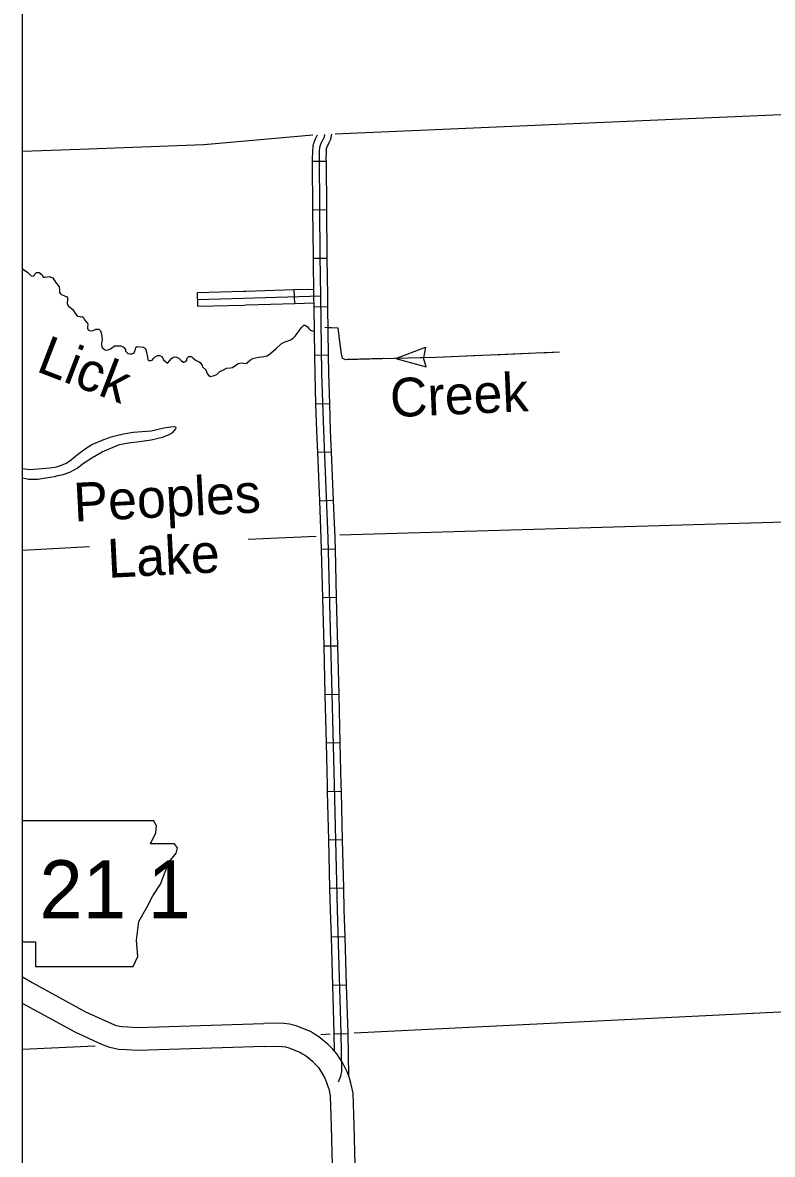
# Model space of a CAD drawing. Extents: x 1164457 to 1439835, y 1590918 to 1773502.
# Drawn here: x 1246398 to 1254561, y 1653578 to 1665903 of the extents above; entities that cross this region are included whole.
import ezdxf

# ---------------------------------------------------------------- set-up
doc = ezdxf.new("R2010")
doc.units = 0
for name, color, linetype in [('Level 1', 7, 'Continuous'), ('Level 10', 7, 'Continuous'), ('Level 21', 7, 'Continuous'), ('Level 32', 7, 'Continuous'), ('Level 35', 7, 'Continuous'), ('Level 43', 7, 'Continuous'), ('Level 45', 7, 'Continuous'), ('Level 5', 7, 'Continuous'), ('R_Draft', 7, 'Continuous')]:
    doc.layers.add(name, color=color, linetype=linetype)

msp = doc.modelspace()

# ---------------------------------------------------------------- linework, layer by layer
at = {"layer": 'Level 1'}
for points in [[(1260189, 1665083), (1255108, 1664914), (1254987, 1664912), (1249802, 1664688)], [(1249558, 1664676), (1248370, 1664574), (1247021, 1664523), (1246398, 1664499)]]:
    msp.add_lwpolyline(points, dxfattribs=at)
at = {"layer": 'Level 10'}
for points in [[(1246398, 1655512), (1246503, 1655450), (1247083, 1655130), (1247364, 1655002), (1247418, 1654982), (1247478, 1654969), (1247543, 1654965), (1247649, 1654960), (1249023, 1655002)], [(1249031, 1654753), (1247648, 1654710), (1247530, 1654715), (1247442, 1654720), (1247347, 1654742), (1247269, 1654770), (1246971, 1654907), (1246398, 1655222)], [(1250061, 1651737), (1250008, 1653894), (1249995, 1654244), (1249973, 1654353), (1249956, 1654409), (1249934, 1654468), (1249911, 1654519), (1249880, 1654577), (1249852, 1654621), (1249818, 1654672), (1249772, 1654726), (1249721, 1654778), (1249665, 1654823), (1249622, 1654858), (1249577, 1654885), (1249531, 1654914), (1249375, 1654978), (1249304, 1654994), (1249243, 1655002), (1249157, 1655006), (1249024, 1655002)], [(1249030, 1654753), (1249155, 1654756), (1249222, 1654753), (1249259, 1654748), (1249298, 1654739), (1249417, 1654690), (1249446, 1654672), (1249478, 1654653), (1249509, 1654628), (1249553, 1654593), (1249587, 1654557), (1249618, 1654522), (1249641, 1654486), (1249664, 1654451), (1249687, 1654408), (1249703, 1654373), (1249719, 1654329), (1249730, 1654291), (1249746, 1654214), (1249758, 1653886), (1249811, 1651731)]]:
    msp.add_lwpolyline(points, dxfattribs=at)
at = {"layer": 'Level 21'}
for p, q in [((1247857, 1657154), (1247822, 1657213)), ((1247848, 1657078), (1247857, 1657154)), ((1247789, 1656960), (1247848, 1657078)), ((1248051, 1656960), (1247789, 1656960)), ((1248085, 1656917), (1248051, 1656960)), ((1248068, 1656858), (1248085, 1656917)), ((1247992, 1656765), (1248068, 1656858)), ((1247950, 1656655), (1247992, 1656765)), ((1247899, 1656520), (1247950, 1656655)), ((1247815, 1656393), (1247899, 1656520)), ((1247755, 1656274), (1247815, 1656393)), ((1247662, 1656114), (1247755, 1656274)), ((1247637, 1655911), (1247662, 1656114)), ((1246398, 1655901), (1246410, 1655894)), ((1246410, 1655894), (1246537, 1655894)), ((1246537, 1655894), (1246537, 1655623)), ((1247654, 1655733), (1247637, 1655911)), ((1247603, 1655623), (1247654, 1655733)), ((1246537, 1655623), (1247603, 1655623))]:
    msp.add_line(p, q, dxfattribs=at)
msp.add_lwpolyline([(1246398, 1657213), (1247822, 1657213)], dxfattribs=at)
at = {"layer": 'Level 32'}
for p, q in [((1249705, 1664391), (1249555, 1664390)), ((1249709, 1663863), (1249559, 1663862)), ((1249714, 1663336), (1249564, 1663333)), ((1249722, 1662808), (1249572, 1662806)), ((1249729, 1662280), (1249579, 1662278)), ((1249742, 1661753), (1249592, 1661749)), ((1249761, 1661226), (1249611, 1661220)), ((1249783, 1660699), (1249633, 1660693)), ((1249803, 1660170), (1249653, 1660166)), ((1249816, 1659642), (1249666, 1659638)), ((1249830, 1659114), (1249680, 1659111)), ((1249843, 1658587), (1249693, 1658583)), ((1249856, 1658059), (1249706, 1658055)), ((1249869, 1657531), (1249719, 1657527)), ((1249882, 1657003), (1249732, 1656999)), ((1249894, 1656475), (1249744, 1656472)), ((1249909, 1655948), (1249759, 1655943)), ((1249925, 1655420), (1249775, 1655415)), ((1249941, 1654892), (1249791, 1654888))]:
    msp.add_line(p, q, dxfattribs=at)
for points in [[(1249555, 1664390), (1249554, 1664418), (1249556, 1664499), (1249560, 1664559), (1249569, 1664591), (1249580, 1664620), (1249588, 1664638), (1249610, 1664680)], [(1249837, 1654369), (1249864, 1654430), (1249875, 1654480), (1249866, 1654899), (1249825, 1656240), (1249792, 1657601), (1249725, 1660289), (1249676, 1661460), (1249657, 1662082), (1249645, 1662929), (1249638, 1663360), (1249629, 1664418), (1249631, 1664496), (1249634, 1664546), (1249640, 1664567), (1249649, 1664590), (1249656, 1664605), (1249669, 1664631), (1249684, 1664659), (1249689, 1664684)], [(1249705, 1664391), (1249704, 1664418), (1249706, 1664492), (1249708, 1664534), (1249711, 1664543), (1249718, 1664560), (1249724, 1664573), (1249735, 1664596), (1249755, 1664634), (1249766, 1664687)], [(1249559, 1663862), (1249555, 1664390)], [(1249709, 1663863), (1249705, 1664391)], [(1249564, 1663333), (1249563, 1663360), (1249559, 1663862)], [(1249714, 1663336), (1249713, 1663361), (1249709, 1663863)], [(1249572, 1662806), (1249570, 1662928), (1249564, 1663333)], [(1249722, 1662808), (1249720, 1662930), (1249714, 1663336)], [(1249579, 1662278), (1249572, 1662806)], [(1249729, 1662280), (1249722, 1662808)], [(1249592, 1661749), (1249582, 1662080), (1249579, 1662278)], [(1249742, 1661753), (1249732, 1662083), (1249729, 1662280)], [(1249611, 1661220), (1249601, 1661457), (1249592, 1661749)], [(1249761, 1661226), (1249751, 1661462), (1249742, 1661753)], [(1249633, 1660693), (1249611, 1661220)], [(1249783, 1660699), (1249761, 1661226)], [(1249653, 1660166), (1249650, 1660287), (1249633, 1660693)], [(1249803, 1660170), (1249800, 1660292), (1249783, 1660699)], [(1249666, 1659638), (1249653, 1660166)], [(1249816, 1659642), (1249803, 1660170)], [(1249680, 1659111), (1249666, 1659638)], [(1249830, 1659114), (1249816, 1659642)], [(1249693, 1658583), (1249680, 1659111)], [(1249843, 1658587), (1249830, 1659114)], [(1249706, 1658055), (1249693, 1658583)], [(1249856, 1658059), (1249843, 1658587)], [(1249719, 1657527), (1249717, 1657600), (1249706, 1658055)], [(1249869, 1657531), (1249867, 1657603), (1249856, 1658059)], [(1249732, 1656999), (1249719, 1657527)], [(1249882, 1657003), (1249869, 1657531)], [(1249744, 1656472), (1249732, 1656999)], [(1249894, 1656475), (1249882, 1657003)], [(1249759, 1655943), (1249750, 1656238), (1249744, 1656472)], [(1249909, 1655948), (1249900, 1656242), (1249894, 1656475)], [(1249775, 1655415), (1249759, 1655943)], [(1249925, 1655420), (1249909, 1655948)], [(1249791, 1654888), (1249791, 1654897), (1249775, 1655415)], [(1249941, 1654892), (1249941, 1654901), (1249925, 1655420)], [(1249795, 1654709), (1249791, 1654888)], [(1249951, 1654432), (1249941, 1654892)]]:
    msp.add_lwpolyline(points, dxfattribs=at)
at = {"layer": 'Level 35'}
msp.add_line((1249158, 1662355), (1249211, 1662404), dxfattribs=at)
for points in [[(1246398, 1663220), (1246455, 1663183), (1246492, 1663147), (1246516, 1663141), (1246529, 1663154), (1246538, 1663173), (1246550, 1663181), (1246565, 1663183), (1246578, 1663181), (1246609, 1663156), (1246621, 1663131), (1246641, 1663131), (1246670, 1663135), (1246688, 1663137), (1246715, 1663126), (1246727, 1663122), (1246756, 1663078), (1246794, 1663024), (1246799, 1662991), (1246799, 1662964), (1246815, 1662945), (1246860, 1662925), (1246874, 1662922), (1246886, 1662905), (1246886, 1662878), (1246882, 1662859), (1246882, 1662841), (1246896, 1662814), (1246945, 1662780), (1246973, 1662733), (1246995, 1662706), (1247019, 1662701), (1247030, 1662699), (1247048, 1662704), (1247059, 1662692), (1247073, 1662665)], [(1247073, 1662665), (1247098, 1662639), (1247104, 1662632), (1247108, 1662608), (1247106, 1662593), (1247105, 1662576), (1247113, 1662558), (1247135, 1662546), (1247166, 1662549), (1247196, 1662564), (1247216, 1662564), (1247228, 1662564), (1247245, 1662548), (1247253, 1662526), (1247260, 1662487), (1247265, 1662450), (1247257, 1662414), (1247257, 1662392), (1247265, 1662365), (1247299, 1662335), (1247328, 1662340), (1247355, 1662352), (1247382, 1662374), (1247402, 1662382), (1247420, 1662382), (1247444, 1662382), (1247466, 1662382), (1247498, 1662367), (1247518, 1662345), (1247518, 1662326), (1247542, 1662299), (1247566, 1662296), (1247586, 1662296), (1247609, 1662304), (1247625, 1662336), (1247632, 1662366), (1247646, 1662377), (1247683, 1662374), (1247714, 1662367), (1247734, 1662355), (1247748, 1662313), (1247758, 1662259), (1247760, 1662237), (1247770, 1662223), (1247792, 1662223), (1247807, 1662228), (1247822, 1662244), (1247841, 1662262), (1247868, 1662279), (1247893, 1662279), (1247917, 1662262), (1247933, 1662230), (1247974, 1662196), (1247999, 1662222), (1248020, 1662247), (1248036, 1662261), (1248055, 1662262), (1248074, 1662261), (1248097, 1662249), (1248124, 1662225), (1248144, 1662206), (1248158, 1662206), (1248177, 1662215), (1248187, 1662228), (1248187, 1662247), (1248195, 1662257), (1248209, 1662267), (1248220, 1662267), (1248236, 1662267), (1248254, 1662249), (1248286, 1662223), (1248313, 1662212), (1248330, 1662200), (1248351, 1662168), (1248358, 1662156), (1248392, 1662122), (1248407, 1662083), (1248417, 1662066), (1248439, 1662051), (1248473, 1662056), (1248513, 1662071), (1248545, 1662103), (1248586, 1662120), (1248618, 1662141), (1248659, 1662144), (1248684, 1662147), (1248709, 1662166), (1248750, 1662191), (1248778, 1662198), (1248804, 1662195), (1248822, 1662191), (1248843, 1662195), (1248854, 1662208), (1248880, 1662230), (1248905, 1662244), (1248934, 1662254), (1248966, 1662261), (1249024, 1662266), (1249060, 1662276), (1249099, 1662304), (1249158, 1662355)], [(1249211, 1662404), (1249245, 1662424), (1249278, 1662435), (1249315, 1662450), (1249343, 1662465), (1249366, 1662488), (1249408, 1662546), (1249430, 1662580), (1249459, 1662607), (1249474, 1662609), (1249490, 1662599), (1249498, 1662590), (1249513, 1662571), (1249532, 1662552), (1249576, 1662538)], [(1246786, 1660970), (1246841, 1660982), (1246913, 1661008), (1246990, 1661051), (1247061, 1661104), (1247152, 1661165), (1247263, 1661227), (1247451, 1661307), (1247549, 1661326), (1247669, 1661342), (1247799, 1661361), (1247921, 1661389), (1247987, 1661413), (1248034, 1661439), (1248067, 1661481), (1248071, 1661492), (1248065, 1661499), (1248037, 1661502), (1247934, 1661485), (1247798, 1661455), (1247601, 1661441), (1247498, 1661420), (1247360, 1661388), (1247277, 1661359), (1247157, 1661308), (1247094, 1661270), (1246997, 1661195), (1246931, 1661140), (1246879, 1661107), (1246818, 1661079), (1246763, 1661063)], [(1246477, 1661032), (1246398, 1661045)], [(1246763, 1661063), (1246749, 1661059), (1246694, 1661050), (1246477, 1661032)], [(1246398, 1660944), (1246432, 1660940), (1246461, 1660932), (1246562, 1660932), (1246652, 1660944), (1246746, 1660961), (1246786, 1660970)]]:
    msp.add_lwpolyline(points, dxfattribs=at)
at = {"layer": 'Level 43'}
for points in [[(1252242, 1662313), (1250896, 1662257), (1250443, 1662247), (1249916, 1662232), (1249879, 1662247), (1249867, 1662313), (1249833, 1662577), (1249689, 1662583)], [(1249866, 1662320), (1249833, 1662577), (1249725, 1662581)], [(1250462, 1662247), (1250783, 1662367), (1250761, 1662254)], [(1250330, 1662244), (1249934, 1662233)], [(1250857, 1662256), (1250462, 1662247)], [(1250462, 1662247), (1250792, 1662155), (1250761, 1662254)], [(1251385, 1662277), (1250989, 1662261)], [(1251913, 1662299), (1251517, 1662283)], [(1252242, 1662313), (1252044, 1662305)]]:
    msp.add_lwpolyline(points, dxfattribs=at)
at = {"layer": 'Level 45'}
for p, q in [((1248305, 1662814), (1248301, 1662964)), ((1249361, 1662845), (1249356, 1662995))]:
    msp.add_line(p, q, dxfattribs=at)
for points in [[(1248301, 1662964), (1248802, 1662977), (1248828, 1662978)], [(1248828, 1662978), (1249356, 1662995)], [(1249356, 1662995), (1249569, 1663002)], [(1248303, 1662889), (1248804, 1662902), (1249645, 1662929)], [(1248305, 1662814), (1248806, 1662827), (1248833, 1662828)], [(1248833, 1662828), (1249361, 1662845)], [(1249361, 1662845), (1249571, 1662852)]]:
    msp.add_lwpolyline(points, dxfattribs=at)
at = {"layer": 'Level 5'}
for points in [[(1255065, 1660473), (1249850, 1660320)], [(1248855, 1660277), (1249594, 1660310)], [(1246398, 1660157), (1247125, 1660199)], [(1250007, 1654902), (1255234, 1655159)], [(1249646, 1654884), (1249746, 1654889)], [(1246398, 1654722), (1247189, 1654761)]]:
    msp.add_lwpolyline(points, dxfattribs=at)
at = {"layer": 'R_Draft'}
msp.add_lwpolyline([(1246398, 1678582), (1349820, 1678582), (1349820, 1614471), (1246398, 1614471)], close=True, dxfattribs=at)

# ---------------------------------------------------------------- texts
at = {"layer": 'Level 21'}
msp.add_text('21 1', height=633.6, dxfattribs=at).set_placement((1246581, 1656147))
at = {"layer": 'Level 35'}
for s, rotation, p in [('Lick', 338.929, (1246533, 1662111)), ('Creek', 2.5508, (1250407, 1661605)), ('Peoples', 2.9133, (1246962, 1660468)), ('Lake', 2.9133, (1247330, 1659856))]:
    msp.add_text(s, height=422, rotation=rotation, dxfattribs=at).set_placement(p)

doc.saveas('drawing.dxf')
